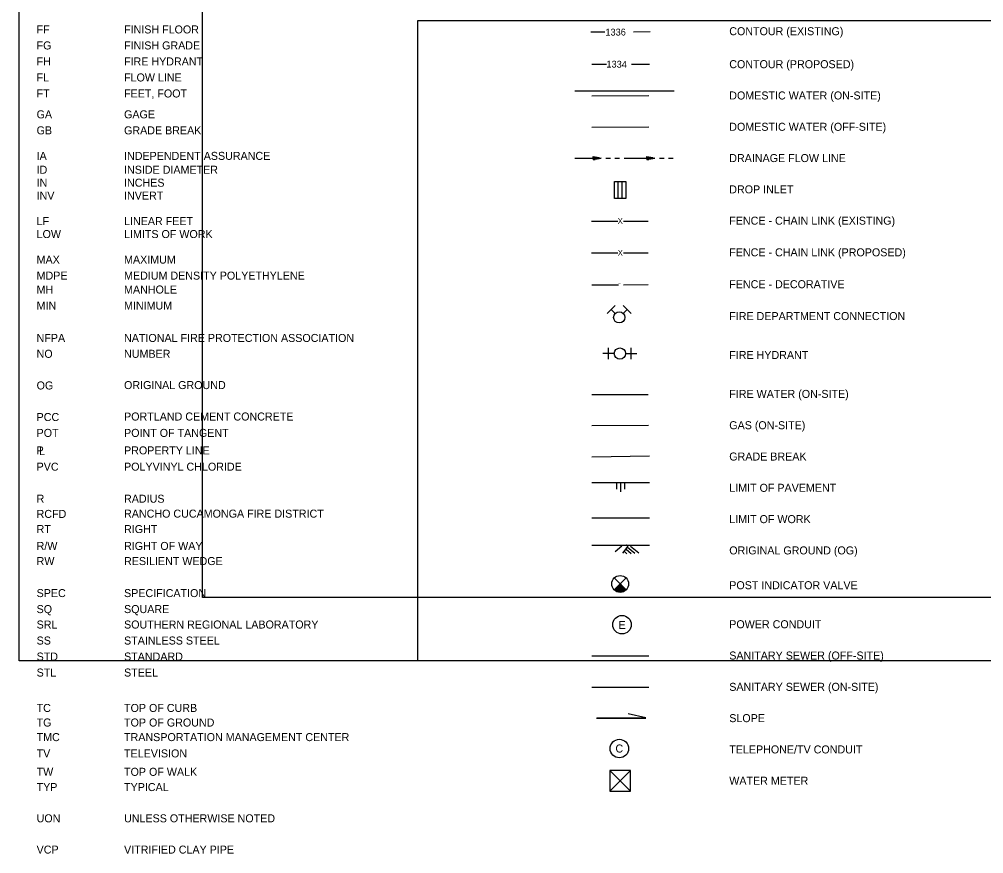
# Model space of a CAD drawing. Extents: x 6711682 to 6713077, y 1869209 to 1870525.
# Drawn here: x 6711682 to 6712525, y 1869209 to 1869939 of the extents above; entities that cross this region are included whole.
import ezdxf

# ---------------------------------------------------------------- set-up
doc = ezdxf.new("R2010")
doc.units = 0
for name, color, linetype in [('Contour Grad(41)', 7, 'Continuous'), ('Control (1)', 7, 'Continuous'), ('Exist Utils (5)', 7, 'Continuous'), ('G-TTLB-VIEW', 7, 'Continuous'), ('New Utility (40)', 7, 'Continuous'), ('Nongeo Data(60)', 7, 'Continuous'), ('RW (exist) (31)', 7, 'Continuous'), ('Sheet Format(10)', 7, 'Continuous')]:
    doc.layers.add(name, color=color, linetype=linetype)

msp = doc.modelspace()

# ---------------------------------------------------------------- linework, layer by layer
at = {"layer": 'Contour Grad(41)'}
for p, q in [((6712182.35, 1869899.33), (6712195.42, 1869899.34)), ((6712217.2, 1869899.34), (6712232.89, 1869899.35)), ((6712182.35, 1869555.83), (6712232.89, 1869556.62)), ((6712182.35, 1869354.37), (6712232.29, 1869354.37))]:
    msp.add_line(p, q, dxfattribs=at)
at = {"layer": 'Control (1)'}
for p, q in [((6712232.89, 1869533.04), (6712182.35, 1869533.04)), ((6712232.89, 1869478.28), (6712182.35, 1869478.28))]:
    msp.add_line(p, q, dxfattribs=at)
at = {"layer": 'Exist Utils (5)'}
for p, q in [((6712182.35, 1869844.25), (6712232.25, 1869844.41)), ((6712205.62, 1869781.72), (6712205.62, 1869796.72)), ((6712209.02, 1869781.72), (6712209.02, 1869796.72)), ((6712182.3, 1869762.12), (6712205.13, 1869762.12)), ((6712210.13, 1869762.12), (6712231.75, 1869762.12)), ((6712182.35, 1869381.75), (6712232.29, 1869381.75)), ((6712216.31, 1869281.51), (6712198.32, 1869281.51)), ((6712198.32, 1869281.51), (6712198.32, 1869263.52)), ((6712198.32, 1869281.51), (6712216.31, 1869263.52)), ((6712198.32, 1869263.52), (6712216.31, 1869281.51)), ((6712216.31, 1869281.51), (6712198.32, 1869281.51)), ((6712198.32, 1869281.51), (6712198.32, 1869263.52)), ((6712198.32, 1869281.51), (6712216.31, 1869263.52)), ((6712198.32, 1869263.52), (6712216.31, 1869281.51)), ((6712216.31, 1869281.51), (6712198.32, 1869281.51)), ((6712198.32, 1869281.51), (6712198.32, 1869263.52)), ((6712198.32, 1869281.51), (6712216.31, 1869263.52)), ((6712198.32, 1869263.52), (6712216.31, 1869281.51)), ((6712216.31, 1869281.51), (6712198.32, 1869281.51)), ((6712198.32, 1869281.51), (6712198.32, 1869263.52)), ((6712198.32, 1869281.51), (6712216.31, 1869263.52)), ((6712198.32, 1869263.52), (6712216.31, 1869281.51)), ((6712216.31, 1869263.52), (6712216.31, 1869281.51)), ((6712216.31, 1869263.52), (6712216.31, 1869281.51)), ((6712216.31, 1869263.52), (6712216.31, 1869281.51)), ((6712216.31, 1869263.52), (6712216.31, 1869281.51)), ((6712198.32, 1869263.52), (6712216.31, 1869263.52)), ((6712198.32, 1869263.52), (6712216.31, 1869263.52)), ((6712198.32, 1869263.52), (6712216.31, 1869263.52)), ((6712198.32, 1869263.52), (6712216.31, 1869263.52))]:
    msp.add_line(p, q, dxfattribs=at)
msp.add_lwpolyline([(6712212.32, 1869781.72), (6712202.32, 1869781.72), (6712202.32, 1869796.72), (6712212.32, 1869796.72)], close=True, dxfattribs=at)
at = {"layer": 'G-TTLB-VIEW'}
for points in [[(6711681.56, 1870497.47), (6713076.58, 1870497.47), (6713076.58, 1869377.45), (6711681.56, 1869377.45)], [(6711841.98, 1870272.86), (6712888.25, 1870272.86), (6712888.25, 1869432.85), (6711841.98, 1869432.85)], [(6712030.32, 1869937.46), (6712727.83, 1869937.46), (6712727.83, 1869377.45), (6712030.32, 1869377.45)]]:
    msp.add_lwpolyline(points, close=True, dxfattribs=at)
at = {"layer": 'New Utility (40)'}
for p, q in [((6712182.35, 1869871.63), (6712232.25, 1869871.78)), ((6712182.3, 1869734.22), (6712205.18, 1869734.26)), ((6712210.18, 1869734.27), (6712231.8, 1869734.3)), ((6712182.35, 1869706.36), (6712205.84, 1869706.4)), ((6712210.09, 1869706.41), (6712231.85, 1869706.45)), ((6712203, 1869688.27), (6712196.04, 1869681.31)), ((6712203, 1869681.31), (6712199.52, 1869684.79)), ((6712216.92, 1869681.31), (6712209.96, 1869688.27)), ((6712213.44, 1869684.79), (6712209.96, 1869681.31)), ((6712197.18, 1869641.29), (6712197.18, 1869651.13)), ((6712216.87, 1869641.29), (6712216.87, 1869651.13)), ((6712202.11, 1869646.21), (6712192.26, 1869646.21)), ((6712211.95, 1869646.21), (6712221.79, 1869646.21)), ((6712182.35, 1869610.42), (6712231.75, 1869610.5)), ((6712182.35, 1869583.21), (6712232.05, 1869583.45)), ((6712212.54, 1869449.88), (6712202.1, 1869439.44)), ((6712212.54, 1869439.44), (6712202.1, 1869449.88)), ((6712207.32, 1869444.66), (6712202.57, 1869439.01)), ((6712207.32, 1869444.66), (6712203.08, 1869438.62)), ((6712207.32, 1869444.66), (6712203.63, 1869438.27)), ((6712207.32, 1869444.66), (6712204.2, 1869437.97)), ((6712207.32, 1869444.66), (6712204.79, 1869437.73)), ((6712207.32, 1869444.66), (6712205.41, 1869437.53)), ((6712207.32, 1869444.66), (6712206.04, 1869437.39)), ((6712207.32, 1869444.66), (6712206.67, 1869437.31)), ((6712207.32, 1869444.66), (6712212.54, 1869439.44)), ((6712207.32, 1869444.66), (6712212.06, 1869439.01)), ((6712207.32, 1869444.66), (6712211.55, 1869438.62)), ((6712207.32, 1869444.66), (6712211.01, 1869438.27)), ((6712207.32, 1869444.66), (6712210.44, 1869437.97)), ((6712207.32, 1869444.66), (6712209.84, 1869437.73)), ((6712207.32, 1869444.66), (6712209.23, 1869437.53)), ((6712207.32, 1869444.66), (6712208.6, 1869437.39)), ((6712207.32, 1869444.66), (6712207.96, 1869437.31)), ((6712207.32, 1869444.66), (6712207.32, 1869437.28))]:
    msp.add_line(p, q, dxfattribs=at)
for centre, radius in [((6712206.48, 1869677.83), 4.92), ((6712207.03, 1869646.21), 4.92), ((6712207.32, 1869444.66), 7.38), ((6712208.89, 1869409), 8.1), ((6712206.57, 1869300.68), 8.1)]:
    msp.add_circle(centre, radius, dxfattribs=at)
at = {"layer": 'Nongeo Data(60)'}
for p, q in [((6712167.7, 1869875.98), (6712254.53, 1869875.98)), ((6712183.7, 1869817.17), (6712183.7, 1869818.67)), ((6712183.7, 1869818.67), (6712190.7, 1869817.17)), ((6712183.7, 1869817.17), (6712183.7, 1869815.67)), ((6712190.7, 1869817.17), (6712183.7, 1869815.67)), ((6712230.7, 1869817.17), (6712230.7, 1869818.67)), ((6712230.7, 1869818.67), (6712237.7, 1869817.17)), ((6712230.7, 1869817.17), (6712230.7, 1869815.67)), ((6712237.7, 1869817.17), (6712230.7, 1869815.67)), ((6712204.12, 1869533.04), (6712204.12, 1869527.51)), ((6712207.62, 1869533.04), (6712207.62, 1869525.12)), ((6712211.12, 1869533.04), (6712211.12, 1869527.51)), ((6712208.71, 1869477.74), (6712203.01, 1869472.66)), ((6712214.12, 1869477.7), (6712209.42, 1869471.72)), ((6712210.92, 1869473.43), (6712212.98, 1869470.9)), ((6712212.48, 1869475.15), (6712216.88, 1869471.15)), ((6712212.87, 1869478.87), (6712212.98, 1869478.74)), ((6712213.66, 1869476.8), (6712220.1, 1869471.5)), ((6712216.31, 1869477.68), (6712223.52, 1869471.74)), ((6712229.86, 1869327.6), (6712214.29, 1869331.04)), ((6712186.71, 1869327.29), (6712229.86, 1869327.29)), ((6712186.8, 1869327.6), (6712229.86, 1869327.6))]:
    msp.add_line(p, q, dxfattribs=at)
for points in [[(6712193.73, 1869927.3), (6712181.68, 1869927.24)], [(6712233.45, 1869927.48), (6712218.99, 1869927.42)], [(6712167.7, 1869817.17), (6712183.7, 1869817.17)], [(6712183.7, 1869818.29), (6712185.45, 1869818.29)], [(6712183.7, 1869817.92), (6712187.2, 1869817.92)], [(6712183.7, 1869817.54), (6712188.95, 1869817.54)], [(6712183.7, 1869817.17), (6712190.7, 1869817.17)], [(6712183.7, 1869816.79), (6712188.95, 1869816.79)], [(6712183.7, 1869816.42), (6712187.2, 1869816.42)], [(6712183.7, 1869816.04), (6712185.45, 1869816.04)], [(6712194.7, 1869817.17), (6712198.7, 1869817.17)], [(6712202.7, 1869817.17), (6712206.7, 1869817.17)], [(6712210.7, 1869817.17), (6712214.7, 1869817.17)], [(6712214.7, 1869817.17), (6712230.7, 1869817.17)], [(6712230.7, 1869818.29), (6712232.45, 1869818.29)], [(6712230.7, 1869817.92), (6712234.2, 1869817.92)], [(6712230.7, 1869817.54), (6712235.95, 1869817.54)], [(6712230.7, 1869817.17), (6712237.7, 1869817.17)], [(6712230.7, 1869816.79), (6712235.95, 1869816.79)], [(6712230.7, 1869816.42), (6712234.2, 1869816.42)], [(6712230.7, 1869816.04), (6712232.45, 1869816.04)], [(6712241.7, 1869817.17), (6712245.7, 1869817.17)], [(6712249.7, 1869817.17), (6712253.7, 1869817.17)]]:
    msp.add_lwpolyline(points, dxfattribs=at)
at = {"layer": 'RW (exist) (31)'}
msp.add_line((6712182.35, 1869502.41), (6712232.89, 1869502.41), dxfattribs=at)

# ---------------------------------------------------------------- texts
at = {"layer": 'Exist Utils (5)'}
msp.add_text('X', height=5, dxfattribs=at).set_placement((6712205.13, 1869759.62))
at = {"layer": 'New Utility (40)'}
for s, height, p in [('X', 5, (6712205.18, 1869731.76)), ('¯', 2.5, (6712205.69, 1869704.75))]:
    msp.add_text(s, height=height, rotation=0.09974, dxfattribs=at).set_placement(p)
at = {"layer": 'Nongeo Data(60)'}
for s, rotation, p in [('1336', 0.26983, (6712194.39, 1869924.3)), ('1334', 359.16102, (6712195.25, 1869896.4))]:
    msp.add_text(s, height=6, rotation=rotation, dxfattribs=at).set_placement(p)
at = {"layer": 'Sheet Format(10)'}
for s, p in [('FF', (6711696.72, 1869926.19)), ('FINISH FLOOR', (6711773.23, 1869926.19)), ('CONTOUR (EXISTING)', (6712302.73, 1869924.63)), ('FG', (6711696.72, 1869912.19)), ('FINISH GRADE', (6711773.23, 1869912.19)), ('FH', (6711696.72, 1869898.19)), ('FIRE HYDRANT', (6711773.23, 1869898.19)), ('CONTOUR (PROPOSED)', (6712302.73, 1869895.79)), ('FL', (6711696.72, 1869884.19)), ('FLOW LINE', (6711773.23, 1869884.19)), ('FT', (6711696.72, 1869870.19)), ('FEET, FOOT', (6711773.23, 1869870.19)), ('DOMESTIC WATER (ON-SITE)', (6712302.73, 1869868.42)), ('GA', (6711696.72, 1869851.91)), ('GAGE', (6711773.23, 1869851.91)), ('GB', (6711696.72, 1869837.91)), ('GRADE BREAK', (6711773.23, 1869837.91)), ('DOMESTIC WATER (OFF-SITE)', (6712302.73, 1869841.04)), ('IA', (6711696.72, 1869815.6)), ('INDEPENDENT ASSURANCE', (6711773.23, 1869815.6)), ('DRAINAGE FLOW LINE', (6712302.73, 1869813.67)), ('ID', (6711696.72, 1869803.47)), ('INSIDE DIAMETER', (6711773.23, 1869803.47)), ('IN', (6711696.72, 1869792.15)), ('INCHES', (6711773.23, 1869792.15)), ('INV', (6711696.72, 1869780.84)), ('INVERT', (6711773.23, 1869780.84)), ('DROP INLET', (6712302.73, 1869786.29)), ('LF', (6711696.72, 1869758.52)), ('LINEAR FEET', (6711773.23, 1869758.52)), ('FENCE - CHAIN LINK (EXISTING)', (6712302.73, 1869758.91)), ('LOW', (6711696.72, 1869747.21)), ('LIMITS OF WORK', (6711773.23, 1869747.21)), ('FENCE - CHAIN LINK (PROPOSED)', (6712302.73, 1869731.21)), ('MAX', (6711696.72, 1869724.86)), ('MAXIMUM', (6711773.23, 1869724.86)), ('MDPE', (6711696.72, 1869710.86)), ('MEDIUM DENSITY POLYETHYLENE', (6711773.23, 1869710.86)), ('FENCE - DECORATIVE', (6712302.73, 1869703.34)), ('MH', (6711696.72, 1869698.69)), ('MANHOLE', (6711773.23, 1869698.69)), ('MIN', (6711696.72, 1869684.69)), ('MINIMUM', (6711773.23, 1869684.69)), ('FIRE DEPARTMENT CONNECTION', (6712302.73, 1869675.47)), ('NFPA', (6711696.72, 1869656.33)), ('NATIONAL FIRE PROTECTION ASSOCIATION', (6711773.23, 1869656.33)), ('NO', (6711696.72, 1869642.46)), ('NUMBER', (6711773.23, 1869642.46)), ('FIRE HYDRANT', (6712302.73, 1869641.42)), ('OG', (6711696.72, 1869614.77)), ('ORIGINAL GROUND', (6711773.23, 1869615.11)), ('FIRE WATER (ON-SITE)', (6712302.73, 1869607.37)), ('PCC', (6711696.72, 1869587.15)), ('PORTLAND CEMENT CONCRETE ', (6711773.23, 1869587.61)), ('GAS (ON-SITE)', (6712302.73, 1869579.99)), ('POT', (6711696.72, 1869573.28)), ('POINT OF TANGENT', (6711773.23, 1869573.28)), ('P', (6711696.72, 1869557.98)), ('L', (6711698.99, 1869557.37)), ('PROPERTY LINE', (6711773.23, 1869557.98)), ('GRADE BREAK', (6712302.73, 1869552.62)), ('PVC', (6711696.72, 1869543.73)), ('POLYVINYL CHLORIDE', (6711773.23, 1869543.73)), ('LIMIT OF PAVEMENT', (6712302.73, 1869525.24)), ('R', (6711696.72, 1869515.73)), ('RADIUS', (6711773.23, 1869515.73)), ('RCFD', (6711696.72, 1869502.41)), ('RANCHO CUCAMONGA FIRE DISTRICT', (6711773.23, 1869502.66)), ('LIMIT OF WORK', (6712302.73, 1869497.86)), ('RT', (6711696.72, 1869489.16)), ('RIGHT', (6711773.23, 1869489.16)), ('R/W', (6711696.72, 1869474.41)), ('RIGHT OF WAY', (6711773.23, 1869474.41)), ('ORIGINAL GROUND (OG)', (6712302.73, 1869470.49)), ('RW', (6711696.72, 1869461.16)), ('RESILIENT WEDGE', (6711773.23, 1869461.16)), ('SPEC', (6711696.72, 1869433.16)), ('SPECIFICATION', (6711773.23, 1869433.16)), ('POST INDICATOR VALVE', (6712302.73, 1869440.04)), ('SQ', (6711696.72, 1869419.16)), ('SQUARE', (6711773.23, 1869419.16)), ('SRL', (6711696.72, 1869405.66)), ('SOUTHERN REGIONAL LABORATORY', (6711773.23, 1869405.66)), ('E', (6712205.85, 1869405.24)), ('POWER CONDUIT', (6712302.73, 1869405.91)), ('SS', (6711696.72, 1869391.66)), ('STAINLESS STEEL', (6711773.23, 1869391.66)), ('STD', (6711696.72, 1869377.66)), ('STANDARD', (6711773.23, 1869377.66)), ('SANITARY SEWER (OFF-SITE)', (6712302.73, 1869378.54)), ('STL', (6711696.72, 1869363.66)), ('STEEL', (6711773.23, 1869363.66)), ('SANITARY SEWER (ON-SITE)', (6712302.73, 1869351.16)), ('TC', (6711696.72, 1869332.69)), ('TOP OF CURB', (6711773.23, 1869332.69)), ('SLOPE', (6712302.73, 1869323.78)), ('TG', (6711696.72, 1869319.94)), ('TOP OF GROUND', (6711773.23, 1869319.94)), ('TMC', (6711696.72, 1869307.19)), ('TRANSPORTATION MANAGEMENT CENTER', (6711773.23, 1869307.19)), ('C', (6712203.15, 1869297.2)), ('TV', (6711696.72, 1869292.92)), ('TELEVISION', (6711773.23, 1869292.92)), ('TELEPHONE/TV CONDUIT', (6712302.73, 1869296.41)), ('TW', (6711696.72, 1869276.82)), ('TOP OF WALK', (6711773.23, 1869276.82)), ('TYP', (6711696.72, 1869263.48)), ('TYPICAL', (6711773.23, 1869263.48)), ('WATER METER', (6712302.73, 1869269.03)), ('UON', (6711696.72, 1869236.14)), ('UNLESS OTHERWISE NOTED', (6711773.23, 1869236.14)), ('VCP', (6711696.72, 1869208.79)), ('VITRIFIED CLAY PIPE', (6711773.23, 1869208.79))]:
    msp.add_text(s, height=7, dxfattribs=at).set_placement(p)

doc.saveas('drawing.dxf')
